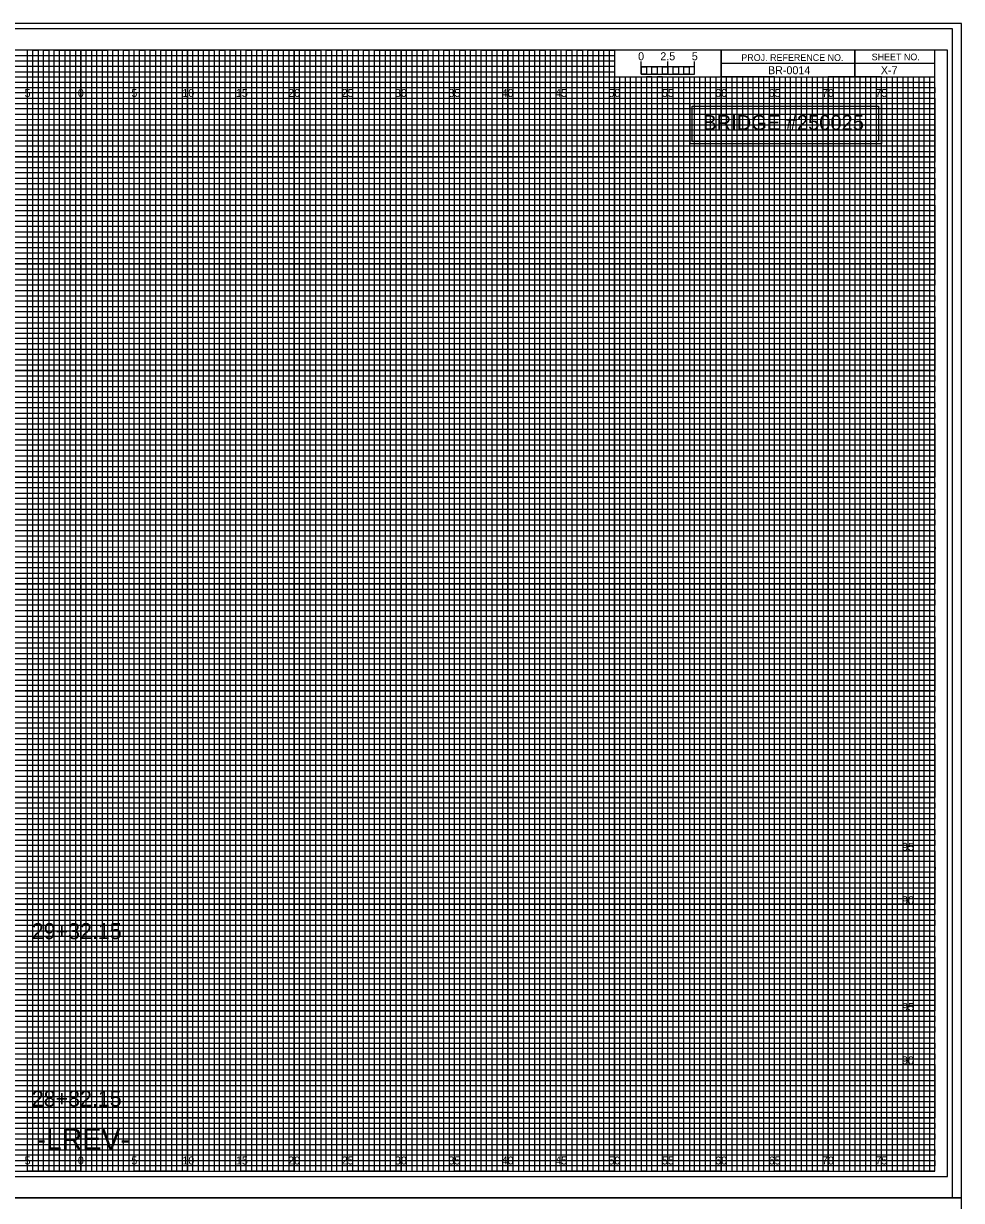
# Model space of a CAD drawing. Extents: x -8 to 533, y -20 to 768.
# Drawn here: x 74.6 to 162.5, y 657.2 to 767.5 of the extents above; entities that cross this region are included whole.
import ezdxf

# ---------------------------------------------------------------- set-up
doc = ezdxf.new("R2010")
doc.units = 0
for name, color, linetype in [('Prop Dimension', 7, 'Continuous'), ('Prop Grid Mask', 7, 'Continuous'), ('Prop XS Alignment Label', 7, 'Continuous'), ('Prop XS Bar Scale Labels', 7, 'Continuous'), ('Prop XS Elevation Labels', 7, 'Continuous'), ('Prop XS Offset Labels', 7, 'Continuous'), ('Prop XS Project Number', 7, 'Continuous'), ('Prop XS Sheet Number', 7, 'Continuous'), ('Prop XS Station Labels', 7, 'Continuous'), ('Sheet Cross Section CELL', 7, 'Continuous'), ('Sheet Cross Section Grid Major CELL', 7, 'Continuous'), ('Sheet Cross Section Grid Middle CELL', 7, 'Continuous'), ('Sheet Cross Section Grid Minor 1 CELL', 7, 'Continuous'), ('Sheet Cross Section Grid Minor 2 CELL', 7, 'Continuous'), ('Sheet Cross Section Scale CELL', 7, 'Continuous'), ('Sheet Cutting Line CELL', 7, 'Continuous'), ('Sheet DOT Grid CELL', 7, 'Continuous'), ('Sheet Plot Border Inside CELL', 7, 'Continuous'), ('Sheet Plot Border Outside CELL', 7, 'Continuous'), ('WEI Plot Border', 7, 'Continuous')]:
    doc.layers.add(name, color=color, linetype=linetype)

msp = doc.modelspace()

# ---------------------------------------------------------------- linework, layer by layer
at = {"layer": 'Prop Dimension'}
msp.add_lwpolyline([(137.26, 759.75), (154.74, 759.75), (154.74, 756.46), (137.26, 756.46)], close=True, dxfattribs=at)
at = {"layer": 'Prop Grid Mask'}
msp.add_lwpolyline([(137.08, 760), (155, 760), (155, 756.24), (137.08, 756.24)], close=True, dxfattribs=at)
at = {"layer": 'Sheet Cross Section CELL'}
for p, q in [((152.5, 765), (152.5, 762.5)), ((152.5, 762.5), (152.5, 765)), ((160, 763.75), (140, 763.75)), ((140, 763.75), (140, 762.5)), ((140, 762.5), (160, 762.5))]:
    msp.add_line(p, q, dxfattribs=at)
for points in [[(160, 765), (0, 765), (0, 660), (160, 660)], [(140, 765), (130, 765), (130, 762.51), (140, 762.51)], [(160, 765), (140, 765), (140, 762.5), (160, 762.5)]]:
    msp.add_lwpolyline(points, close=True, dxfattribs=at)
at = {"layer": 'Sheet Cross Section Grid Major CELL'}
for p, q in [((75, 765), (70, 765)), ((75, 660), (75, 765)), ((85, 765), (80, 765)), ((80, 765), (80, 660)), ((85, 660), (85, 765)), ((95, 765), (90, 765)), ((90, 765), (90, 660)), ((95, 660), (95, 765)), ((105, 765), (100, 765)), ((100, 765), (100, 660)), ((105, 660), (105, 765)), ((115, 765), (110, 765)), ((110, 765), (110, 660)), ((115, 660), (115, 765)), ((125, 765), (120, 765)), ((120, 765), (120, 660)), ((125, 660), (125, 765)), ((130, 765), (130, 660)), ((135, 660), (135, 762.5)), ((145, 762.5), (140, 762.5)), ((140, 762.5), (140, 660)), ((145, 660), (145, 762.5)), ((155, 762.5), (150, 762.5)), ((150, 762.5), (150, 660)), ((155, 660), (155, 762.5)), ((80, 660), (75, 660)), ((90, 660), (85, 660)), ((100, 660), (95, 660)), ((110, 660), (105, 660)), ((120, 660), (115, 660)), ((130, 660), (125, 660)), ((140, 660), (135, 660)), ((150, 660), (145, 660)), ((160, 660), (155, 660)), ((160, 660), (160, 660))]:
    msp.add_line(p, q, dxfattribs=at)
for points in [[(0, 760), (160, 760), (160, 755), (0, 755)], [(0, 750), (160, 750), (160, 745), (0, 745)], [(0, 740), (160, 740), (160, 735), (0, 735)], [(0, 730), (160, 730), (160, 725), (0, 725)], [(0, 720), (160, 720), (160, 715), (0, 715)], [(0, 710), (160, 710), (160, 705), (0, 705)], [(0, 700), (160, 700), (160, 695), (0, 695)], [(0, 690), (160, 690), (160, 685), (0, 685)], [(0, 680), (160, 680), (160, 675), (0, 675)], [(0, 670), (160, 670), (160, 665), (0, 665)]]:
    msp.add_lwpolyline(points, dxfattribs=at)
at = {"layer": 'Sheet Cross Section Grid Middle CELL'}
for points in [[(72.5, 660), (77.5, 660), (77.5, 765), (82.5, 765), (82.5, 660), (87.5, 660), (87.5, 765), (92.5, 765), (92.5, 660), (97.5, 660), (97.5, 765), (102.5, 765), (102.5, 660), (107.5, 660), (107.5, 765), (112.5, 765), (112.5, 660), (117.5, 660), (117.5, 765), (122.5, 765), (122.5, 660), (127.5, 660), (127.5, 765), (129.97, 765), (130, 765), (130, 762.5), (132.5, 762.5), (132.5, 660), (137.5, 660), (137.5, 762.5), (142.5, 762.5), (142.5, 660), (147.5, 660), (147.5, 762.5), (152.5, 762.5), (152.5, 660), (157.5, 660), (157.5, 762.5)], [(0, 762.5), (137.5, 762.5)], [(0, 752.5), (160, 752.5), (160, 757.5), (0, 757.5)], [(0, 742.5), (160, 742.5), (160, 747.5), (0, 747.5)], [(0, 732.5), (160, 732.5), (160, 737.5), (0, 737.5)], [(0, 722.5), (160, 722.5), (160, 727.5), (0, 727.5)], [(0, 712.5), (160, 712.5), (160, 717.5), (0, 717.5)], [(0, 702.5), (160, 702.5), (160, 707.5), (0, 707.5)], [(0, 692.5), (160, 692.5), (160, 697.5), (0, 697.5)], [(0, 682.5), (160, 682.5), (160, 687.5), (0, 687.5)], [(0, 672.5), (160, 672.5), (160, 677.5), (0, 677.5)], [(0, 662.5), (160, 662.5), (160, 667.5), (0, 667.5)]]:
    msp.add_lwpolyline(points, dxfattribs=at)
at = {"layer": 'Sheet Cross Section Grid Minor 1 CELL'}
for p, q in [((0, 764.5), (130, 764.5)), ((130, 764.5), (130, 763.99)), ((130, 763.99), (0, 763.99)), ((0, 763.5), (130, 763.5)), ((130, 762.95), (0, 762.95)), ((130, 763.5), (130, 762.95)), ((0, 762), (160, 762))]:
    msp.add_line(p, q, dxfattribs=at)
for points in [[(0, 761.5), (135, 761.5), (160, 761.5), (160, 761), (0, 761)], [(0, 760.5), (160, 760.5), (160, 759.5), (0, 759.5)], [(0, 759), (160, 759), (160, 758.5), (0, 758.49)], [(0, 758), (160, 758), (160, 757), (0, 757)], [(0, 756.5), (160, 756.5), (160, 756), (0, 756)], [(0, 755.5), (160, 755.5), (160, 754.5), (0, 754.5)], [(0, 754), (160, 754), (160, 753.5), (0, 753.5)], [(0, 753), (160, 753), (160, 752), (0, 752)], [(0, 751.5), (160, 751.5), (160, 751), (0, 751)], [(0, 750.5), (160, 750.5), (160, 749.5), (0, 749.5)], [(0, 749), (160, 749), (160, 748.5), (0, 748.5)], [(0, 748), (160, 748), (160, 746.98), (160, 746.5), (160, 746), (0, 746)], [(0, 747), (160, 747), (160, 746.5), (0, 746.5)], [(0, 745.5), (160, 745.5), (160, 744.5), (0, 744.51)], [(0, 744.51), (160, 744.5), (160, 744), (0, 744)], [(0, 743.5), (160, 743.5), (160, 743), (0, 743)], [(0, 742), (160, 742), (160, 741.5), (0, 741.5)], [(0, 741), (160, 741), (160, 740.5), (0, 740.5)], [(-0.04, 739.45), (160, 739.45), (160, 738.94), (-0.04, 738.94)], [(0, 738.5), (160, 738.5), (160, 738), (0, 738)], [(0, 737), (160, 737), (160, 736.5), (0, 736.5)], [(0, 736), (160, 736), (160, 735.5), (0, 735.5)], [(0, 734.5), (160, 734.5), (160, 734), (0, 734)], [(0, 733.5), (160, 733.5), (160, 733), (0, 733)], [(0, 732), (160, 732), (160, 731.5), (0, 731.5)], [(0, 731), (160, 731), (160, 730.5), (0, 730.5)], [(0, 729.5), (160, 729.5), (160, 728.99), (0, 729)], [(0, 728.5), (160, 728.5), (160, 728), (0, 728)], [(0, 727), (160, 727), (160, 726.5), (0, 726.5)], [(0, 726), (160, 726), (160, 725.5), (0, 725.5)], [(0, 724.5), (160, 724.5), (160, 724), (0, 724)], [(0, 723.5), (160, 723.5), (160, 723), (0, 723)], [(0, 722), (160, 722), (160, 721.5), (0, 721.5)], [(0, 721), (160, 721), (160, 720.5), (0, 720.5)], [(0, 719.5), (160, 719.5), (160, 719), (0, 719)], [(0, 718.5), (160.03, 718.46), (160, 718), (0, 718)], [(0, 717), (160, 717), (160, 716.5), (0, 716.5)], [(0, 716), (160, 716), (160, 715.5), (0, 715.5)], [(0, 714.5), (160, 714.5), (160, 714), (0, 714)], [(0, 713.5), (160, 713.5), (160, 713), (0, 713)], [(0, 712), (160, 712), (160, 711.5), (0, 711.5)], [(0, 711), (160, 711), (160, 710.5), (0, 710.5)], [(0, 709.5), (160, 709.5), (160, 709), (0, 709)], [(0, 708.5), (160, 708.5), (160, 708), (0, 708)], [(0, 707), (160, 707), (160, 706.5), (0, 706.5)], [(0, 706), (160, 706), (160, 705.5), (0, 705.5)], [(0, 704.5), (160, 704.5), (160, 704), (0, 704)], [(0, 703.5), (160, 703.5), (160, 703), (0, 703)], [(0, 702), (160, 702), (160, 701.5), (0, 701.5)], [(0, 701), (160, 701), (160, 700.5), (0, 700.5)], [(0, 699.5), (160, 699.5), (160, 698.99), (0, 699)], [(0, 698.5), (160, 698.5), (160, 698), (0, 698)], [(0, 697), (160, 697), (160, 696.5), (0, 696.5)], [(0, 696), (160, 696), (160, 695.5), (0, 695.5)], [(0, 694.5), (160, 694.5), (160, 694), (0, 694)], [(0, 693.5), (160, 693.5), (160, 693), (0, 693)], [(0, 692), (160, 692), (160, 691.5), (0, 691.5)], [(0, 691), (160, 691), (160, 690.5), (0, 690.5)], [(0, 689.5), (160, 689.5), (160, 689), (0, 689)], [(0, 688.5), (160.03, 688.46), (160, 688), (0, 688)], [(0, 687), (160, 687), (160, 686.5), (0, 686.5)], [(0, 686), (160, 686), (160, 685.5), (0, 685.5)], [(0, 684.5), (160, 684.5), (160, 684), (0, 684)], [(0, 683.5), (160, 683.5), (160, 683), (0, 683)], [(0, 682), (160, 682), (160, 681.5), (0, 681.5)], [(0, 681), (160, 681), (160, 680.5), (0, 680.5)], [(0, 679.5), (160, 679.5), (160, 679), (0, 679)], [(0, 678.5), (160, 678.5), (160, 678), (0, 678)], [(0, 677), (160, 677), (160, 676.5), (0, 676.5)], [(0, 676), (160, 676), (160, 675.5), (0, 675.5)], [(0, 674.5), (160, 674.5), (160, 674), (0, 674)], [(0, 673.5), (160, 673.5), (160, 673), (0, 673)], [(0, 672), (160, 672), (160, 671.5), (0, 671.5)], [(0, 671), (160, 671), (160, 670.5), (0, 670.5)], [(0, 669.5), (160, 669.5), (160, 669), (0, 669)], [(0, 668.5), (160, 668.5), (160, 668), (0, 668)], [(0, 667), (160, 667), (160, 666.5), (0, 666.5)], [(0, 666), (160, 666), (160, 665.5), (0, 665.5)], [(0, 664.5), (160, 664.5), (160, 664), (0, 664)], [(0, 663.5), (160, 663.5), (160, 663), (0, 663)], [(0, 662), (160, 662), (160, 661.5), (0, 661.5)], [(0, 661), (160, 661), (160, 660.5), (0, 660.5)]]:
    msp.add_lwpolyline(points, dxfattribs=at)
at = {"layer": 'Sheet Cross Section Grid Minor 2 CELL'}
for p, q in [((133.5, 762.5), (133, 762.5)), ((133, 762.5), (133, 660)), ((133.5, 660), (133.5, 762.5)), ((134.5, 762.5), (134, 762.5)), ((134, 762.5), (134, 660)), ((134.5, 660), (134.5, 762.5)), ((133, 660), (132.5, 660)), ((134, 660), (133.5, 660))]:
    msp.add_line(p, q, dxfattribs=at)
for points in [[(75, 660), (75.5, 660), (75.5, 765), (76, 765), (76, 660)], [(76, 660), (76.5, 660), (76.5, 765), (77, 765), (77, 660)], [(77.5, 660), (78, 660), (78, 765), (78.5, 765), (78.5, 660)], [(78.5, 660), (79, 660), (79, 765), (79.5, 765), (79.5, 660)], [(80, 660), (80.5, 660), (80.5, 765), (81, 765), (81, 660)], [(81, 660), (81.5, 660), (81.5, 765), (82, 765), (82, 660)], [(82.5, 660), (83, 660), (83, 765), (83.5, 765), (83.5, 660)], [(83.5, 660), (84, 660), (84, 765), (84.5, 765), (84.5, 660)], [(85, 660), (85.5, 660), (85.5, 765), (86, 765), (86, 660)], [(86, 660), (86.5, 660), (86.5, 765), (87, 765), (87, 660)], [(87.5, 660), (88, 660), (88, 765), (88.5, 765), (88.5, 660)], [(88.5, 660), (89, 660), (89, 765), (89.5, 765), (89.5, 660)], [(90, 660), (90.5, 660), (90.5, 765), (91, 765), (91, 660)], [(91, 660), (91.5, 660), (91.5, 765), (92, 765), (92, 660)], [(92.5, 660), (93, 660), (93, 765), (93.5, 765), (93.5, 660)], [(93.5, 660), (94, 660), (94, 765), (94.5, 765), (94.5, 660)], [(95, 660), (95.5, 660), (95.5, 765), (96, 765), (96, 660)], [(96, 660), (96.5, 660), (96.5, 765), (97, 765), (97, 660)], [(97.5, 660), (98, 660), (98, 765), (98.5, 765), (98.5, 660)], [(98.5, 660), (99, 660), (99, 765), (99.5, 765), (99.5, 660)], [(100, 660), (100.5, 660), (100.5, 765), (101, 765), (101, 660)], [(101, 660), (101.5, 660), (101.5, 765), (102, 765), (102, 660)], [(102.5, 660), (103, 660), (103, 765), (103.5, 765), (103.5, 660)], [(103.5, 660), (104, 660), (104, 765), (104.5, 765), (104.5, 660)], [(105, 660), (105.5, 660), (105.5, 765), (106, 765), (106, 660)], [(106, 660), (106.5, 660), (106.5, 765), (107, 765), (107, 660)], [(107.5, 660), (108, 660), (108, 765), (108.5, 765), (108.5, 660)], [(108.5, 660), (109, 660), (109, 765), (109.5, 765), (109.5, 660)], [(110, 660), (110.5, 660), (110.5, 765), (111, 765), (111, 660)], [(111, 660), (111.5, 660), (111.5, 765), (112, 765), (112, 660)], [(112.5, 660), (113, 660), (113, 765), (113.5, 765), (113.5, 660)], [(113.5, 660), (114, 660), (114, 765), (114.5, 765), (114.5, 660)], [(115, 660), (115.5, 660), (115.5, 765), (116, 765), (116, 660)], [(116, 660), (116.5, 660), (116.5, 765), (117, 765), (117, 660)], [(117.5, 660), (118, 660), (118, 765), (118.5, 765), (118.5, 660)], [(118.5, 660), (119, 660), (119, 765), (119.5, 765), (119.5, 660)], [(120, 660), (120.5, 660), (120.5, 765), (121, 765), (121, 660)], [(121, 660), (121.5, 660), (121.5, 765), (122, 765), (122, 660)], [(122.5, 660), (123, 660), (123, 765), (123.5, 765), (123.5, 660)], [(123.5, 660), (124, 660), (124, 765), (124.5, 765), (124.5, 660)], [(125, 660), (125.5, 660), (125.5, 765), (126, 765), (126, 660)], [(126, 660), (126.5, 660), (126.5, 765), (127, 765), (127, 660)], [(127.5, 660), (128, 660), (128, 765), (128.5, 765), (128.5, 660)], [(128.5, 660), (129, 660), (129, 765), (129.5, 765), (129.5, 660)], [(130, 660), (130.5, 660), (130.5, 762.5), (131.01, 762.5), (131.01, 660)], [(131, 660), (131.5, 660), (131.5, 762.5), (132, 762.5), (132, 660)], [(135, 660), (135.49, 660), (135.49, 762.5), (136, 762.5), (136, 660)], [(136, 660), (136.5, 660), (136.5, 762.5), (137.03, 762.5), (137.03, 660)], [(137.5, 660), (138, 660), (138, 762.5), (138.5, 762.5), (138.5, 660)], [(138.5, 660), (139, 660), (139, 762.5), (139.5, 762.5), (139.5, 660)], [(140, 660), (140.5, 660), (140.5, 762.5), (141, 762.5), (141, 660)], [(141, 660), (141.5, 660), (141.5, 762.5), (142, 762.5), (142, 660)], [(142.5, 660), (143, 660), (143, 762.5), (143.5, 762.5), (143.5, 660)], [(143.5, 660), (144, 660), (144, 762.5), (144.5, 762.5), (144.5, 660)], [(145, 660), (145.5, 660), (145.5, 762.5), (146, 762.5), (146, 660)], [(146, 660), (146.5, 660), (146.5, 762.5), (147, 762.5), (147, 660)], [(147.5, 660), (148, 660), (148, 762.5), (148.5, 762.5), (148.5, 660)], [(148.5, 660), (149, 660), (149, 762.5), (149.5, 762.5), (149.5, 660)], [(150, 660), (150.5, 660), (150.5, 762.5), (151, 762.5), (151, 660)], [(151, 660), (151.5, 660), (151.5, 762.5), (152, 762.5), (152, 660)], [(152.5, 660), (153, 660), (153, 762.5), (153.5, 762.5), (153.5, 660)], [(153.5, 660), (154, 660), (154, 762.5), (154.5, 762.5), (154.5, 660)], [(155, 660), (155.5, 660), (155.5, 762.5), (156, 762.5), (156, 660)], [(156, 660), (156.5, 660), (156.5, 762.5), (157, 762.5), (157, 660)], [(157.5, 660), (158, 660), (158, 762.5), (158.5, 762.5), (158.5, 660)], [(158.5, 660), (159, 660), (159, 762.5), (159.5, 762.5), (159.5, 660)]]:
    msp.add_lwpolyline(points, dxfattribs=at)
at = {"layer": 'Sheet Cross Section Scale CELL'}
for p, q in [((132.5, 762.75), (132.5, 763.95)), ((132.5, 763.45), (132.5, 763.95)), ((135, 762.75), (135, 763.95)), ((137.5, 762.75), (137.5, 763.95)), ((137.5, 763.45), (137.5, 763.95))]:
    msp.add_line(p, q, dxfattribs=at)
for points in [[(137.5, 763.45), (132.5, 763.45), (132.5, 762.75), (137.5, 762.75)], [(132.5, 763.45), (133, 763.45), (133, 762.75), (132.5, 762.75)], [(133.5, 763.45), (134, 763.45), (134, 762.75), (133.5, 762.75)], [(134.5, 763.45), (135, 763.45), (135, 762.75), (134.5, 762.75)], [(135.5, 763.45), (136, 763.45), (136, 762.75), (135.5, 762.75)], [(136.5, 763.45), (137, 763.45), (137, 762.75), (136.5, 762.75)]]:
    msp.add_lwpolyline(points, close=True, dxfattribs=at)
at = {"layer": 'Sheet Cutting Line CELL'}
for p, q in [((161.65, 767), (-6.7, 767)), ((-6.7, 657.5), (161.65, 657.5))]:
    msp.add_line(p, q, dxfattribs=at)
at = {"layer": 'Sheet DOT Grid CELL'}
for p, q in [((75, 660), (75, 765)), ((80, 660), (80, 765)), ((85, 660), (85, 765)), ((90, 660), (90, 765)), ((95, 660), (95, 765)), ((100, 660), (100, 765)), ((105, 660), (105, 765)), ((110, 660), (110, 765)), ((115, 660), (115, 765)), ((120, 660), (120, 765)), ((125, 660), (125, 765)), ((130, 660), (130, 762.34)), ((135, 660), (135, 762.34)), ((140, 660), (140, 762.34)), ((145, 660), (145, 762.34)), ((150, 660), (150, 762.34)), ((155, 660), (155, 762.34)), ((0, 760), (160, 760)), ((0, 755), (160, 755)), ((0, 750), (160, 750)), ((0, 745), (160, 745)), ((0, 740), (160, 740)), ((0, 735), (160, 735)), ((0, 730), (160, 730)), ((0, 725), (160, 725)), ((0, 720), (160, 720)), ((0, 715), (160, 715)), ((0, 710), (160, 710)), ((0, 705), (160, 705)), ((0, 700), (160, 700)), ((0, 695), (160, 695)), ((0, 690), (160, 690)), ((0, 685), (160, 685)), ((0, 680), (160, 680)), ((0, 675), (160, 675)), ((0, 670), (160, 670)), ((0, 665), (160, 665))]:
    msp.add_line(p, q, dxfattribs=at)
at = {"layer": 'Sheet Plot Border Inside CELL'}
msp.add_lwpolyline([(-5.4, 659.5), (161.2, 659.5), (161.2, 765), (-5.4, 765)], close=True, dxfattribs=at)
at = {"layer": 'Sheet Plot Border Outside CELL'}
msp.add_lwpolyline([(-6.7, 657.5), (161.65, 657.5), (161.65, 767), (-6.7, 767)], close=True, dxfattribs=at)
at = {"layer": 'WEI Plot Border'}
for points in [[(-7.5, 657.5), (162.5, 657.5), (162.5, 767.5), (-7.5, 767.5)], [(-7.5, 547.5), (162.5, 547.5), (162.5, 657.5), (-7.5, 657.5)]]:
    msp.add_lwpolyline(points, close=True, dxfattribs=at)

# ---------------------------------------------------------------- texts
at = {"layer": 'Prop Dimension'}
msp.add_text('BRIDGE #250025', height=1.4062, rotation=360, dxfattribs=at).set_placement((138.31, 757.52))
at = {"layer": 'Prop XS Alignment Label'}
msp.add_text('-LREV-', height=2, dxfattribs=at).set_placement((75.84, 662))
at = {"layer": 'Prop XS Bar Scale Labels'}
for s, p in [('2.5', (134.29, 764.06)), ('5', (137.24, 764.06))]:
    msp.add_text(s, height=0.75, dxfattribs=at).set_placement(p)
at = {"layer": 'Prop XS Elevation Labels'}
for s, p in [('95', (156.94, 690)), ('90', (156.93, 685)), ('95', (156.94, 675)), ('90', (156.93, 670))]:
    msp.add_text(s, height=0.75, dxfattribs=at).set_placement(p)
at = {"layer": 'Prop XS Offset Labels'}
for s, p in [('5', (74.74, 760.62)), ('0', (79.73, 760.62)), ('0', (79.73, 760.62)), ('5', (84.74, 760.62)), ('10', (89.52, 760.62)), ('15', (94.53, 760.62)), ('20', (99.43, 760.62)), ('25', (104.44, 760.62)), ('30', (109.43, 760.62)), ('35', (114.44, 760.62)), ('40', (119.43, 760.62)), ('45', (124.44, 760.62)), ('50', (129.43, 760.62)), ('55', (134.44, 760.62)), ('60', (139.43, 760.62)), ('65', (144.44, 760.62)), ('70', (149.43, 760.62)), ('75', (154.44, 760.62)), ('5', (74.74, 660.62)), ('0', (79.73, 660.62)), ('0', (79.73, 660.62)), ('5', (84.74, 660.62)), ('10', (89.52, 660.62)), ('15', (94.53, 660.62)), ('20', (99.43, 660.62)), ('25', (104.44, 660.62)), ('30', (109.43, 660.62)), ('35', (114.44, 660.62)), ('40', (119.43, 660.62)), ('45', (124.44, 660.62)), ('50', (129.43, 660.62)), ('55', (134.44, 660.62)), ('60', (139.43, 660.62)), ('65', (144.44, 660.62)), ('70', (149.43, 660.62)), ('75', (154.44, 660.62))]:
    msp.add_text(s, height=0.75, dxfattribs=at).set_placement(p)
at = {"layer": 'Prop XS Project Number'}
msp.add_text('BR-0014', height=0.75, dxfattribs=at).set_placement((144.38, 762.75))
at = {"layer": 'Prop XS Sheet Number'}
msp.add_text('X-7', height=0.75, dxfattribs=at).set_placement((154.95, 762.75))
at = {"layer": 'Prop XS Station Labels'}
for s, p in [('29+32.15', (75.41, 681.73)), ('28+82.15', (75.41, 666.05))]:
    msp.add_text(s, height=1.5, dxfattribs=at).set_placement(p)
at = {"layer": 'Sheet Cross Section CELL'}
for s, p in [('PROJ. REFERENCE NO.', (141.88, 764)), ('SHEET NO.', (154.09, 764.06))]:
    msp.add_text(s, height=0.625, dxfattribs=at).set_placement(p)
at = {"layer": 'Sheet Cross Section Scale CELL'}
msp.add_text('0', height=0.75, dxfattribs=at).set_placement((132.21, 764.06))

doc.saveas('drawing.dxf')
